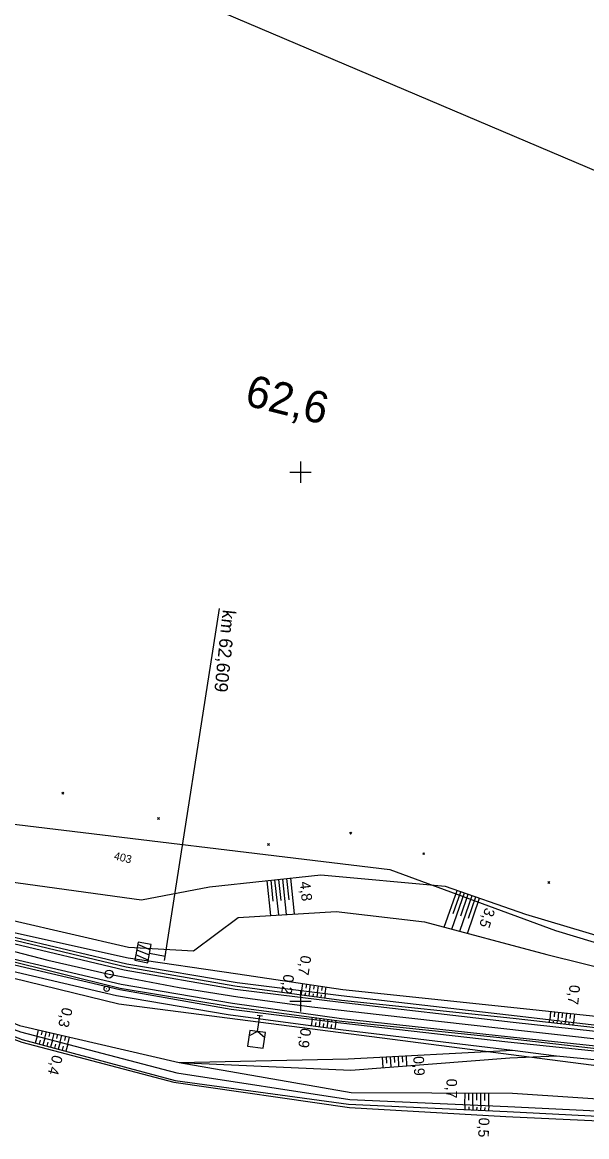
# Model space of a CAD drawing. Extents: x -805636 to -804553, y -1165340 to -1164656.
# Drawn here: x -804952.6 to -804845.9, y -1165125.7 to -1164914.9 of the extents above; entities that cross this region are included whole.
import ezdxf

# ---------------------------------------------------------------- set-up
doc = ezdxf.new("R2010")
doc.units = 0
for name, color, linetype in [('0381KM061-064P - Vrstva 1', 7, 'Continuous'), ('0381KM061-064P - Vrstva 4', 7, 'Continuous'), ('0381KM061-064P - Vrstva 48', 7, 'Continuous'), ('0381KM061-064P - Vrstva 49', 7, 'Continuous'), ('0381KM061-064P - Vrstva 51', 7, 'Continuous'), ('0381KM061-064P - Vrstva 57', 7, 'Continuous'), ('0381KM061-064P - Vrstva 7', 7, 'Continuous'), ('formát', 7, 'Continuous'), ('hran DP - hran DP', 7, 'Continuous'), ('krizky_1000 - Vrstva 1', 7, 'Continuous')]:
    doc.layers.add(name, color=color, linetype=linetype)

msp = doc.modelspace()

# ---------------------------------------------------------------- linework, layer by layer
at = {"layer": '0381KM061-064P - Vrstva 1'}
for points in [[(-805053.13, -1165050.53), (-805043.64, -1165055.76), (-805030.64, -1165062.45), (-805014.61, -1165069.88), (-804997.39, -1165076.92), (-804978.26, -1165083.66), (-804962.13, -1165088.54), (-804947.73, -1165092.28), (-804936.17, -1165094.91), (-804922.95, -1165097.46), (-804911.85, -1165099.22)], [(-804911.85, -1165099.22), (-804897.85, -1165101.07), (-804885.13, -1165102.52)], [(-804885.13, -1165102.52), (-804856.51, -1165105.73), (-804836.78, -1165107.96), (-804807.43, -1165111.28), (-804800.55, -1165112.05)]]:
    msp.add_lwpolyline(points, dxfattribs=at)
at = {"layer": '0381KM061-064P - Vrstva 4'}
for points in [[(-805080.11, -1165031.8), (-805059.18, -1165044.72), (-805045.31, -1165052.51), (-805029.54, -1165060.96), (-805010.72, -1165069.47), (-804990.45, -1165077.48), (-804974.57, -1165082.73), (-804955.28, -1165088.2), (-804932.96, -1165093.51), (-804912.39, -1165097.1), (-804892.28, -1165099.85)], [(-805080.47, -1165032.5), (-805059.19, -1165045.48), (-805045.86, -1165053.03), (-805029.76, -1165061.31), (-805010.76, -1165070.1), (-804990.66, -1165078.03), (-804974.85, -1165083.28), (-804955.57, -1165088.82), (-804933.31, -1165094.09), (-804912.36, -1165097.73), (-804892.37, -1165100.24)], [(-805082.08, -1165035.58), (-805060.58, -1165048.58), (-805047.98, -1165055.77), (-805031.23, -1165064.28), (-805013.07, -1165072.73), (-804991.62, -1165081.24), (-804976.47, -1165086.37), (-804956.64, -1165091.96), (-804934.05, -1165097.54), (-804913.13, -1165101.06), (-804892.22, -1165103.81)], [(-805082.03, -1165034.98), (-805060.37, -1165047.85), (-805047.54, -1165055.28), (-805031.06, -1165063.92), (-805012.89, -1165072.24), (-804991.69, -1165080.62), (-804976.05, -1165085.82), (-804956.42, -1165091.49), (-804933.87, -1165096.82), (-804912.82, -1165100.43), (-804892.24, -1165103.28)], [(-804892.37, -1165100.24), (-804859.84, -1165103.98), (-804840.8, -1165106.06), (-804819.65, -1165108.38), (-804802.7, -1165110.3), (-804799.92, -1165110.56)], [(-804892.28, -1165099.85), (-804859.81, -1165103.25), (-804840.34, -1165105.46), (-804819.52, -1165107.92), (-804802.69, -1165109.64), (-804799.68, -1165110)], [(-804892.24, -1165103.28), (-804860.33, -1165106.74), (-804841.86, -1165108.69), (-804820.53, -1165111.13), (-804802.92, -1165113.13), (-804801.1, -1165113.34)], [(-804892.22, -1165103.81), (-804860.51, -1165107.09), (-804841.9, -1165109.22), (-804820.58, -1165111.74), (-804803.21, -1165114.08), (-804801.49, -1165114.25)]]:
    msp.add_lwpolyline(points, dxfattribs=at)
at = {"layer": '0381KM061-064P - Vrstva 48'}
for p, q in [((-804905.61, -1165083.83), (-804906.31, -1165077.25)), ((-804905.14, -1165081.14), (-804905.57, -1165077.17)), ((-804904.11, -1165083.73), (-804904.83, -1165077.09)), ((-804903.65, -1165081.01), (-804904.08, -1165077.01)), ((-804902.62, -1165083.64), (-804903.34, -1165076.93)), ((-804902.16, -1165080.89), (-804902.59, -1165076.85)), ((-804901.12, -1165083.54), (-804901.85, -1165076.77)), ((-804872.83, -1165086.04), (-804870.41, -1165079.07)), ((-804871.37, -1165086.42), (-804868.99, -1165079.56)), ((-804871.14, -1165083.47), (-804869.7, -1165079.32)), ((-804869.92, -1165086.81), (-804867.58, -1165080.06)), ((-804869.7, -1165083.89), (-804868.29, -1165079.81)), ((-804868.26, -1165084.32), (-804866.87, -1165080.3)), ((-804868.47, -1165087.2), (-804866.16, -1165080.55)), ((-804899.77, -1165098.02), (-804899.57, -1165096.67)), ((-804898.95, -1165097.58), (-804898.83, -1165096.78)), ((-804898.29, -1165098.2), (-804898.09, -1165096.89)), ((-804897.46, -1165097.78), (-804897.35, -1165097)), ((-804896.8, -1165098.39), (-804896.61, -1165097.11)), ((-804895.98, -1165097.98), (-804895.87, -1165097.22)), ((-804895.31, -1165098.58), (-804895.12, -1165097.33)), ((-804899.78, -1165098.02), (-804899.89, -1165098.81)), ((-804899.08, -1165098.43), (-804899.15, -1165098.91)), ((-804898.29, -1165098.2), (-804898.4, -1165099.01)), ((-804897.59, -1165098.62), (-804897.66, -1165099.12)), ((-804896.8, -1165098.39), (-804896.92, -1165099.22)), ((-804896.11, -1165098.82), (-804896.17, -1165099.32)), ((-804895.32, -1165098.58), (-804895.43, -1165099.42)), ((-804897.81, -1165103.45), (-804897.97, -1165104.67)), ((-804897.8, -1165103.45), (-804897.75, -1165103.08)), ((-804897.04, -1165103.4), (-804897.01, -1165103.18)), ((-804896.32, -1165103.64), (-804896.49, -1165104.86)), ((-804896.31, -1165103.64), (-804896.27, -1165103.28)), ((-804895.55, -1165103.59), (-804895.52, -1165103.38)), ((-804894.83, -1165103.83), (-804894.78, -1165103.48)), ((-804894.06, -1165103.78), (-804894.04, -1165103.57)), ((-804893.34, -1165104.02), (-804893.29, -1165103.67)), ((-804852.96, -1165103.52), (-804853.02, -1165104.02)), ((-804852.82, -1165103.53), (-804852.66, -1165101.96)), ((-804852.01, -1165102.99), (-804851.91, -1165102.04)), ((-804851.33, -1165103.71), (-804851.17, -1165102.11)), ((-804850.52, -1165103.15), (-804850.42, -1165102.19)), ((-804849.84, -1165103.88), (-804849.67, -1165102.27)), ((-804849.03, -1165103.32), (-804848.93, -1165102.35)), ((-804848.35, -1165104.05), (-804848.18, -1165102.43)), ((-804949.77, -1165106.66), (-804949.49, -1165105.44)), ((-804948.93, -1165106.36), (-804948.76, -1165105.61)), ((-804948.32, -1165107.04), (-804948.03, -1165105.78)), ((-804897.13, -1165104.03), (-804897.23, -1165104.77)), ((-804895.64, -1165104.23), (-804895.74, -1165104.97)), ((-804894.83, -1165103.83), (-804895, -1165105.06)), ((-804894.16, -1165104.42), (-804894.26, -1165105.16)), ((-804893.35, -1165104.02), (-804893.51, -1165105.26)), ((-804852.24, -1165103.8), (-804852.27, -1165104.11)), ((-804851.47, -1165103.69), (-804851.53, -1165104.19)), ((-804850.75, -1165103.98), (-804850.78, -1165104.28)), ((-804849.98, -1165103.86), (-804850.04, -1165104.36)), ((-804849.26, -1165104.15), (-804849.29, -1165104.44)), ((-804848.49, -1165104.04), (-804848.55, -1165104.53)), ((-804949.79, -1165106.66), (-804950.13, -1165107.96)), ((-804949.2, -1165107.37), (-804949.41, -1165108.15)), ((-804948.34, -1165107.04), (-804948.69, -1165108.34)), ((-804947.75, -1165107.75), (-804947.96, -1165108.54)), ((-804947.47, -1165106.72), (-804947.29, -1165105.95)), ((-804946.89, -1165107.42), (-804947.24, -1165108.73)), ((-804946.86, -1165107.42), (-804946.56, -1165106.12)), ((-804946.02, -1165107.08), (-804945.83, -1165106.29)), ((-804945.44, -1165107.79), (-804945.79, -1165109.12)), ((-804945.41, -1165107.8), (-804945.1, -1165106.46)), ((-804944.56, -1165107.45), (-804944.37, -1165106.63)), ((-804943.96, -1165108.18), (-804943.64, -1165106.8)), ((-804946.3, -1165108.13), (-804946.51, -1165108.92)), ((-804944.85, -1165108.51), (-804945.06, -1165109.31)), ((-804943.98, -1165108.17), (-804944.34, -1165109.5)), ((-804884.38, -1165112.57), (-804884.48, -1165110.6)), ((-804883.67, -1165111.73), (-804883.73, -1165110.56)), ((-804882.88, -1165112.45), (-804882.99, -1165110.52)), ((-804882.18, -1165111.63), (-804882.24, -1165110.48)), ((-804881.39, -1165112.33), (-804881.49, -1165110.44)), ((-804880.68, -1165111.53), (-804880.74, -1165110.4)), ((-804879.89, -1165112.22), (-804879.99, -1165110.36)), ((-804868.92, -1165119.6), (-804868.91, -1165117.37)), ((-804868.17, -1165118.73), (-804868.16, -1165117.37)), ((-804867.42, -1165119.67), (-804867.41, -1165117.37)), ((-804866.67, -1165118.77), (-804866.66, -1165117.38)), ((-804865.92, -1165119.74), (-804865.91, -1165117.38)), ((-804865.17, -1165118.81), (-804865.16, -1165117.38)), ((-804864.42, -1165119.8), (-804864.41, -1165117.38)), ((-804868.92, -1165119.6), (-804868.96, -1165120.51)), ((-804868.18, -1165120), (-804868.21, -1165120.54)), ((-804867.42, -1165119.67), (-804867.46, -1165120.58)), ((-804866.68, -1165120.06), (-804866.71, -1165120.61)), ((-804865.92, -1165119.74), (-804865.96, -1165120.65)), ((-804865.19, -1165120.13), (-804865.21, -1165120.68)), ((-804864.42, -1165119.8), (-804864.46, -1165120.71))]:
    msp.add_line(p, q, dxfattribs=at)
at = {"layer": '0381KM061-064P - Vrstva 49'}
for p, q in [((-804944.72, -1165060.86), (-804945.08, -1165060.51)), ((-804944.72, -1165060.51), (-804945.08, -1165060.86)), ((-804926.67, -1165065.65), (-804927.02, -1165065.3)), ((-804926.67, -1165065.3), (-804927.02, -1165065.65)), ((-804890.35, -1165068.45), (-804890.7, -1165068.09)), ((-804890.35, -1165068.09), (-804890.7, -1165068.45)), ((-804905.87, -1165070.56), (-804906.22, -1165070.21)), ((-804905.87, -1165070.21), (-804906.22, -1165070.56)), ((-804876.55, -1165072.32), (-804876.9, -1165071.96)), ((-804876.55, -1165071.96), (-804876.9, -1165072.32)), ((-804852.89, -1165077.76), (-804853.25, -1165077.4)), ((-804852.89, -1165077.4), (-804853.25, -1165077.76))]:
    msp.add_line(p, q, dxfattribs=at)
for points in [[(-805085.43, -1165039.91), (-805061.8, -1165053.37), (-805034.45, -1165069.27), (-805016.82, -1165079.3), (-804984.87, -1165094.97), (-804952.63, -1165107.29), (-804923.66, -1165115.02), (-804890.91, -1165119.51), (-804860.93, -1165120.87), (-804821.85, -1165122.9), (-804805.33, -1165123.27)], [(-805084.74, -1165039.06), (-805061.55, -1165052.74), (-805034.17, -1165068.7), (-805016.31, -1165078.58), (-804984.31, -1165094.26), (-804952.92, -1165105.84), (-804923.4, -1165113.55), (-804890.69, -1165118.62), (-804860.79, -1165119.97), (-804821.99, -1165121.8), (-804804.98, -1165122.47)], [(-805060.73, -1165049.17), (-805031.5, -1165064.84), (-805013.36, -1165073.14), (-804991.7, -1165081.91), (-804976.67, -1165086.76), (-804957.06, -1165092.46), (-804934.14, -1165097.81), (-804913.12, -1165101.52), (-804892.37, -1165104.14)], [(-805060.73, -1165049.17), (-805047.98, -1165055.77), (-805031.23, -1165064.28), (-805013.07, -1165072.73), (-804991.62, -1165081.24), (-804976.47, -1165086.37), (-804956.64, -1165091.96), (-804934.05, -1165097.54), (-804913.13, -1165101.06), (-804892.22, -1165103.81), (-804860.51, -1165107.09), (-804841.9, -1165109.22), (-804820.58, -1165111.74), (-804811.31, -1165113.56)], [(-805014.74, -1165060.42), (-805013.72, -1165061.35), (-805008.65, -1165063.79), (-805007.41, -1165061.32), (-805005.07, -1165061.94), (-804999.18, -1165065.52), (-804973.34, -1165074.67), (-804953.36, -1165077.67), (-804930.03, -1165080.86)], [(-805032.39, -1165065.25), (-805013.72, -1165073.73), (-804991.69, -1165082.79), (-804976.92, -1165087.4), (-804957.71, -1165093.59), (-804934.8, -1165098.93), (-804913.68, -1165102.56), (-804892.44, -1165105.41)], [(-805033.41, -1165066.35), (-805014.98, -1165076.25), (-804982.53, -1165092.31), (-804953.12, -1165104.6), (-804922.96, -1165111.59), (-804890.43, -1165117.32), (-804859.92, -1165117.39), (-804821.94, -1165119.94), (-804804.42, -1165121.15)], [(-805010.72, -1165069.47), (-804990.45, -1165077.48), (-804974.57, -1165082.73), (-804955.28, -1165088.2), (-804932.96, -1165093.51), (-804912.39, -1165097.1), (-804892.28, -1165099.85), (-804859.81, -1165103.25), (-804840.34, -1165105.46), (-804819.52, -1165107.92), (-804802.69, -1165109.64), (-804799.68, -1165110)], [(-804995.17, -1165073.22), (-804973.67, -1165080.7), (-804954.98, -1165086.86), (-804932.57, -1165091.85), (-804911.87, -1165094.85)], [(-804994.86, -1165072.51), (-804973.16, -1165079.86), (-804954.29, -1165084.75), (-804932.5, -1165089.79), (-804920.22, -1165090.5), (-804911.77, -1165084.22), (-804893.29, -1165083.05), (-804876.57, -1165085.04), (-804853.44, -1165091.21), (-804839.72, -1165094.63), (-804814.35, -1165098.18)], [(-804930.03, -1165080.86), (-804917.17, -1165078.41), (-804896.14, -1165076.16), (-804872.64, -1165078.3), (-804857.5, -1165083.55), (-804838.27, -1165089.29), (-804812.85, -1165092.56), (-804796.39, -1165094.52), (-804793.24, -1165094.87)], [(-804955.12, -1165087.69), (-804932.8, -1165092.95), (-804911.98, -1165096.48), (-804892.31, -1165098.96)], [(-804911.87, -1165094.85), (-804892.03, -1165097.79)], [(-804892.31, -1165098.96), (-804859.08, -1165102.8), (-804835.93, -1165105.5), (-804818.93, -1165107.36), (-804802.32, -1165108.93), (-804799.37, -1165109.27)], [(-804892.03, -1165097.79), (-804859.05, -1165101.29), (-804840.64, -1165103.22)], [(-804892.44, -1165105.41), (-804859.96, -1165109.29), (-804851.61, -1165110.39), (-804821.13, -1165113.33), (-804811.31, -1165113.56)], [(-804892.37, -1165104.14), (-804860.79, -1165107.69), (-804842.05, -1165109.66), (-804820.85, -1165112.11), (-804811.31, -1165113.56)], [(-804922.96, -1165111.59), (-804890.98, -1165110.95), (-804859.96, -1165109.29)], [(-804922.96, -1165111.59), (-804890.49, -1165113.04), (-804860.47, -1165110.71), (-804851.61, -1165110.39)]]:
    msp.add_lwpolyline(points, dxfattribs=at)
at = {"layer": '0381KM061-064P - Vrstva 51'}
msp.add_lwpolyline([(-805085.93, -1165040.55), (-805062.08, -1165054.12), (-805034.69, -1165069.73), (-805017.21, -1165079.65), (-804985.71, -1165095.39), (-804952.66, -1165107.75), (-804923.93, -1165115.31), (-804890.75, -1165120.1), (-804861.18, -1165121.85), (-804821.92, -1165123.67), (-804805.64, -1165124)], dxfattribs=at)
at = {"layer": '0381KM061-064P - Vrstva 7'}
for p, q in [((-804925.59, -1165091.6), (-804915.32, -1165025.75)), ((-804930.94, -1165090.31), (-804928.58, -1165091.28)), ((-804928.39, -1165090.29), (-804930.75, -1165089.33)), ((-804925.73, -1165092.34), (-804925.45, -1165090.86)), ((-804928.77, -1165092.26), (-804931.13, -1165091.29)), ((-804936.58, -1165097.69), (-804936.68, -1165097.67)), ((-804907.2, -1165102.86), (-804908.19, -1165102.73)), ((-804908.11, -1165105.77), (-804907.69, -1165102.79))]:
    msp.add_line(p, q, dxfattribs=at)
for points in [[(-804925.59, -1165091.6), (-804928.53, -1165091.03), (-804928.2, -1165089.31), (-804930.66, -1165088.84), (-804931.32, -1165092.27), (-804928.86, -1165092.75), (-804928.53, -1165091.03)], [(-804908.11, -1165105.77), (-804909.59, -1165105.56), (-804910, -1165108.53), (-804907.03, -1165108.94), (-804906.62, -1165105.97), (-804908.11, -1165105.77)], [(-804906.76, -1165106.96), (-804908.11, -1165105.77), (-804909.73, -1165106.55)]]:
    msp.add_lwpolyline(points, dxfattribs=at)
for centre, radius in [((-804936.17, -1165094.91), 0.75), ((-804936.63, -1165097.68), 0.5)]:
    msp.add_circle(centre, radius, dxfattribs=at)
at = {"layer": 'formát'}
msp.add_line((-804746.36, -1164984.69), (-804939.6, -1164902.47), dxfattribs=at)
at = {"layer": 'hran DP - hran DP'}
for p, q in [((-804991.93, -1165061.99), (-804883.1, -1165075.15)), ((-804883.1, -1165075.15), (-804851.84, -1165086.69)), ((-804851.84, -1165086.69), (-804818.68, -1165096.66)), ((-804934.32, -1165100.62), (-804968.55, -1165092.26)), ((-804802.89, -1165117.55), (-804934.32, -1165100.62))]:
    msp.add_line(p, q, dxfattribs=at)
at = {"layer": 'krizky_1000 - Vrstva 1'}
for points in [[(-804900, -1164998), (-804900, -1165002)], [(-804902, -1165000), (-804898, -1165000)], [(-804900, -1165098), (-804900, -1165102)], [(-804902, -1165100), (-804898, -1165100)]]:
    msp.add_lwpolyline(points, dxfattribs=at)

# ---------------------------------------------------------------- texts
at = {"layer": '0381KM061-064P - Vrstva 48'}
for s, rotation, p in [('4,8', 276.1274, (-804900.15, -1165077.5)), ('3,5', 250.8741, (-804865.05, -1165082.21)), ('0,7', 261.5641, (-804899.92, -1165091.28)), ('0,2', 262.2041, (-804903.16, -1165094.86)), ('0,7', 264.0185, (-804849.13, -1165096.87)), ('0,3', 256.9445, (-804944.98, -1165101.08)), ('0,9', 262.3554, (-804899.94, -1165105.03)), ('0,4', 255.0624, (-804946.83, -1165110.07)), ('0,9', 273.0779, (-804878.69, -1165110.47)), ('0,7', 269.8704, (-804872.42, -1165114.69)), ('0,5', 267.3952, (-804866.27, -1165122.01))]:
    msp.add_text(s, height=2, rotation=rotation, dxfattribs=at).set_placement(p)
at = {"layer": '0381KM061-064P - Vrstva 57'}
msp.add_text('403', height=1.5, rotation=345.9546, dxfattribs=at).set_placement((-804935.37, -1165073.19))
at = {"layer": '0381KM061-064P - Vrstva 7'}
for s, height, rotation, p in [('62,6', 6, 346.0635, (-804910.76, -1164987.27)), ('km 62,609', 2.5, 264.0663, (-804914.69, -1165025.94))]:
    msp.add_text(s, height=height, rotation=rotation, dxfattribs=at).set_placement(p)

doc.saveas('drawing.dxf')
